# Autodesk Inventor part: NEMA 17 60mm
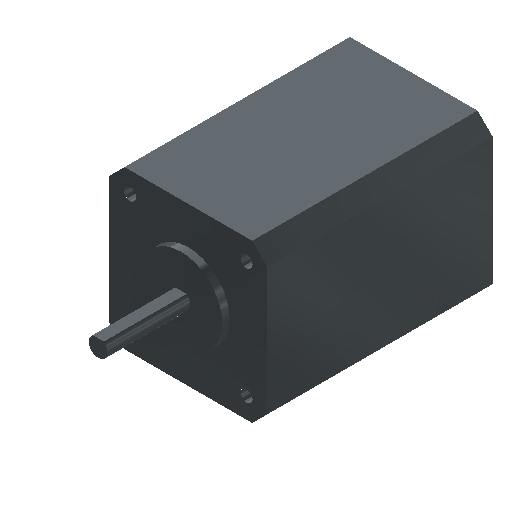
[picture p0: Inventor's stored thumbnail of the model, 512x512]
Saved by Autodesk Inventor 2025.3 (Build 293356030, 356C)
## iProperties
Created: 2026-03
Part Number: NEMA 17 60mm
Material: Generico
Description: NEMA 17
Document SubType Name: Modeling
Designer: R5800u
Density: 1 g/cm^3
Appearance: Grigio ferro
Author: R5800u
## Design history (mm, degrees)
node "NEMA 17"
sketch "Schizzo1"
  geometry: L1 (-2.707, 42)-(39.293, 42); L2 (39.293, 42)-(39.293, 0); L3 (39.293, 0)-(-2.707, 0); L4 (-2.707, 0)-(-2.707, 42); L5 (-2.707, 42)-(39.293, 0); L6 (39.293, 42)-(-2.707, 0); L7 (50.204, 58.756)-(-13.618, 58.756); L8 (-13.618, 58.756)-(-13.618, -16.756); L9 (-13.618, -16.756)-(50.204, -16.756); L10 (50.204, -16.756)-(50.204, 58.756); L11 (50.204, 58.756)-(-13.618, -16.756); L12 (-13.618, 58.756)-(50.204, -16.756); A1 r 2.5 centre (18.293, 21) between (16.793, 23) and (19.793, 23) reference; 1 further point
  constraints: 24 end point, 4 midpoint, 4 parallel, 2 horizontal, 2 perpendicular
  dimensions: "d0" = 42 distance of L2.end L3.end; "d1" = 42 distance of L1.end L2.end
extrude "Estrusione1" cut sketch "Schizzo1" extent not by distance; stored distance "d2" = 0; taper "d3" = 0 deg
sketch "Schizzo2"
  geometry: L1 (1.5, 2)-(-1.5, 2) reference; A1 r 2.5 centre (0, 0) between (-1.5, 2) and (1.5, 2) reference; 1 further point
extrude "Estrusione2" cut sketch "Schizzo2" distance "d4" = 1; taper "d5" = 0 deg
chamfer "Smusso1" distance "d6" = 4; stored, may be unused: second distance "d7" = 2, angle "d8" = 45 deg
sketch "Schizzo3"
  geometry: L1 (38, -38)-(34, -42) reference; L2 (38, -38)-(38, -4) reference; L3 (34, 0)-(38, -4) reference; L4 (34, 0)-(0, 0) reference; L5 (-4, -4)-(0, 0) reference; L6 (-4, -4)-(-4, -38) reference; L7 (0, -42)-(-4, -38) reference; L8 (0, -42)-(34, -42) reference; C1 r 1.6 at (1.5, -5.5) reference; C2 r 1.6 at (1.5, -36.5) reference; C3 r 1.6 at (32.5, -36.5) reference; C4 r 1.6 at (32.5, -5.5) reference; 1 further point
extrude "Estrusione3" join sketch "Schizzo3" distance "d9" = 2; taper "d10" = 0 deg
sketch "Schizzo4"
  geometry: L1 (0, 0)-(-4, -4) reference; L2 (-4, -4)-(-4, -38) reference; L3 (-4, -38)-(0, -42) reference; L4 (0, -42)-(34, -42) reference; L5 (34, -42)-(38, -38) reference; L6 (38, -38)-(38, -4) reference; L7 (38, -4)-(34, 0) reference; L8 (34, 0)-(0, 0) reference; C1 r 1.6 at (32.5, -5.5) reference; C2 r 1.6 at (32.5, -36.5) reference; C3 r 1.6 at (1.5, -36.5) reference; C4 r 1.6 at (1.5, -5.5) reference; 1 further point
extrude "Estrusione4" join sketch "Schizzo4" distance "d11" = 20; taper "d12" = 0 deg
node "Solido1"
node "Linea chiusa proiettata1"
node "Linea chiusa proiettata2"
node "Linea chiusa proiettata3"
